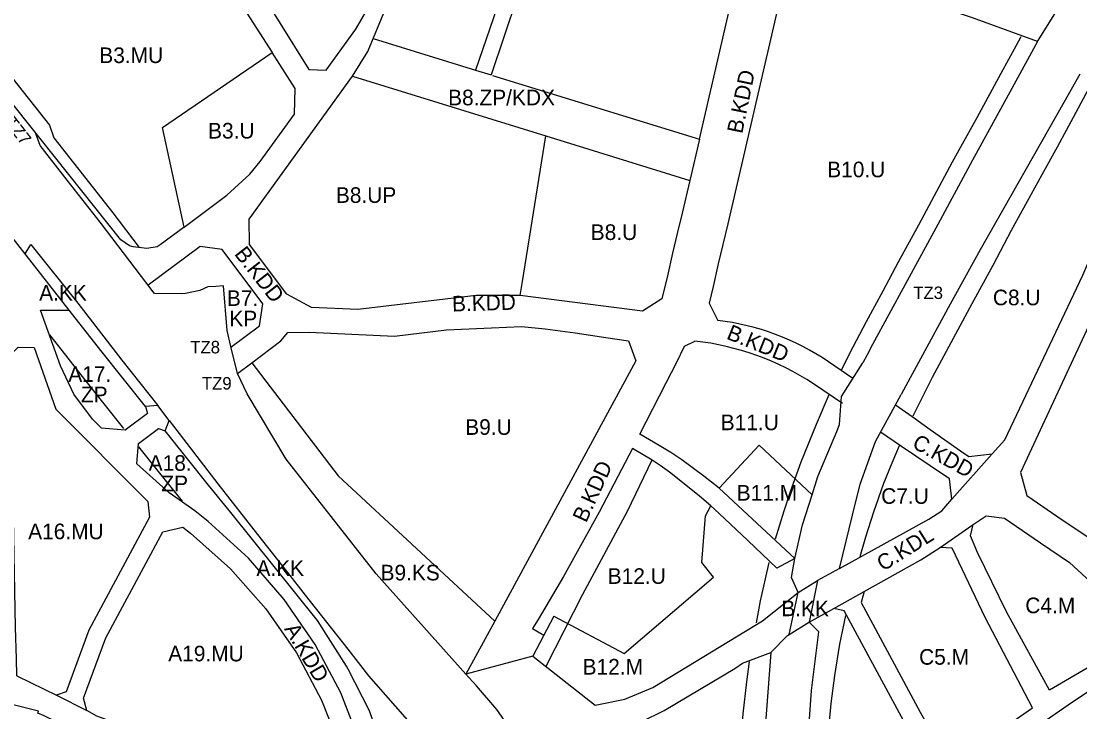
# Model space of a CAD drawing. Extents: x -292612 to -290407, y 29458 to 30862.
# Drawn here: x -292209 to -291531, y 29911 to 30353 of the extents above; entities that cross this region are included whole.
import ezdxf

# ---------------------------------------------------------------- set-up
doc = ezdxf.new("R2010")
doc.units = 0
for name, color, linetype in [('linie_rozgraniczajace', 7, 'Continuous'), ('linie_zabudowy_obowiazujace', 7, 'Continuous'), ('oznaczenia_przeznaczen', 7, 'Continuous')]:
    doc.layers.add(name, color=color, linetype=linetype)

msp = doc.modelspace()

# ---------------------------------------------------------------- linework, layer by layer
at = {"layer": 'linie_rozgraniczajace'}
for p, q in [((-291868.5, 30467.98), (-291918.12, 30321.67)), ((-291859.38, 30464.34), (-291908.23, 30318.61)), ((-291983.72, 30341.92), (-291918.12, 30321.67)), ((-291918.12, 30321.67), (-291908.23, 30318.61)), ((-292178.26, 30167.91), (-292296.67, 30319.14)), ((-291996.9, 30317.77), (-291873.16, 30279.56)), ((-291907.27, 30318.32), (-291774.91, 30277.44)), ((-291873.16, 30279.56), (-291781, 30251.1)), ((-291676.62, 30124.26), (-291692.26, 30134.9)), ((-291683.21, 30108.18), (-291701.82, 30120.84)), ((-291662.21, 30083.74), (-291645.75, 30113.93)), ((-291613.24, 30046.83), (-291587.37, 30075.86)), ((-291762.11, 30053.91), (-291713.69, 30008.82)), ((-291620.76, 30015.91), (-291599.54, 30030.65)), ((-291711.61, 29987.19), (-291699.22, 29994.8)), ((-291688.74, 29976.95), (-291669.49, 29987.68)), ((-291905.83, 29968.86), (-291924.29, 29934.77)), ((-291868.11, 29971.88), (-291881.54, 29946.35)), ((-291717.35, 29960.15), (-291704.43, 29968.23)), ((-291881.54, 29946.35), (-291924.29, 29934.77)), ((-292186.33, 29921.37), (-292166.99, 29911.62)), ((-291812.1, 29904.25), (-291797.36, 29911.59))]:
    msp.add_line(p, q, dxfattribs=at)
for points in [[(-292120.42, 30508.09), (-292127.95, 30497.99), (-292123.99, 30482.41), (-292115.47, 30467.94), (-292024.96, 30322.03), (-292013.84, 30321.64), (-291994.87, 30347.91), (-291984.86, 30365.19), (-291980.5, 30376.62), (-291946.51, 30485.4), (-291943.39, 30494.87)], [(-291996.9, 30317.77), (-291987.17, 30333.65), (-291975.8, 30360.87), (-291971.05, 30373.34), (-291936.99, 30482.35), (-291933.72, 30492.28)], [(-292104.75, 30221.08), (-292119.95, 30209.73), (-292121.9, 30208.54), (-292128.67, 30207.44), (-292137.35, 30208.56), (-292139.58, 30209.07), (-292145.2, 30212.99), (-292221.03, 30308.3), (-292227.7, 30317.87), (-292239.51, 30337.34), (-292236.95, 30350.95), (-292118.95, 30424.55), (-292105.07, 30421.42), (-292048.46, 30333.06)], [(-291774.91, 30277.44), (-291744.32, 30409.82), (-291752.76, 30423.16)], [(-291705.68, 30398.89), (-291717.36, 30393.25), (-291756.65, 30223.21), (-291759.84, 30210), (-291762.77, 30197.66), (-291766.07, 30183.17), (-291768.63, 30172.4), (-291763.14, 30161.41)], [(-291558.46, 30340.08), (-291600, 30355.26), (-291608.33, 30358.01), (-291621.44, 30362.85), (-291641.87, 30370.35), (-291650.9, 30373.9), (-291652.24, 30374.21), (-291663.12, 30379.46), (-291705.68, 30398.89)], [(-291558.46, 30340.08), (-291546.23, 30359.4), (-291536.07, 30377.12)], [(-291558.46, 30340.08), (-291574.9, 30309.97), (-291600, 30264.01), (-291622.25, 30222.87), (-291663.96, 30145.97), (-291667.53, 30139.38), (-291670.29, 30134.33)], [(-292104.75, 30221.08), (-292118.54, 30284.94), (-292048.46, 30333.06)], [(-292104.75, 30221.08), (-292077.28, 30241.6), (-292062.55, 30255.09), (-292056.04, 30263.18), (-292034.16, 30293.49), (-292033.7, 30310.01), (-292048.46, 30333.06)], [(-291889.69, 30177.45), (-291917.73, 30177.45), (-291993.43, 30168.33), (-292023.1, 30169.7), (-292039.07, 30178.18), (-292062.89, 30210.07), (-292063.02, 30226.19), (-291996.9, 30317.77)], [(-291531.35, 30319.11), (-291541.63, 30300.98), (-291595.06, 30206.69), (-291614.29, 30171.79), (-291633.29, 30136.77), (-291642.72, 30119.48), (-291645.75, 30113.93)], [(-291587.37, 30075.86), (-291579.39, 30084.83), (-291529.48, 30190.45), (-291516.54, 30220.35), (-291488.83, 30274.64), (-291492.29, 30289.54)], [(-292070.55, 30127.38), (-292074.87, 30144.76), (-292077.26, 30154.89), (-292079.56, 30183.45), (-292084.41, 30183.2), (-292089.64, 30182.94), (-292094.67, 30180.47), (-292103.75, 30178.69), (-292106.67, 30178.44), (-292123.75, 30178.72), (-292124.51, 30179.63), (-292158.36, 30224.28), (-292179.5, 30251.23), (-292196.93, 30273.47), (-292199.96, 30282.17), (-292200.04, 30282.28)], [(-291889.69, 30177.45), (-291888.2, 30186.35), (-291873.16, 30279.56)], [(-291774.91, 30277.44), (-291781, 30251.1)], [(-291467.65, 30260.81), (-291478.94, 30258.78), (-291538.4, 30130.5), (-291569.22, 30063.92), (-291565.18, 30049.18), (-291545.32, 30035.54), (-291525.45, 30022.09), (-291513.27, 30010.73), (-291511.12, 30008.52), (-291501.73, 29998.88), (-291486.94, 29983.17), (-291484.89, 29980.9)], [(-291781, 30251.1), (-291785.85, 30230.11), (-291789.02, 30216.98), (-291791.99, 30204.46), (-291795.29, 30189.97), (-291798.82, 30175.13), (-291811.39, 30167.38), (-291889.69, 30177.45)], [(-292206.57, 30204.07), (-292202.85, 30210), (-292172.79, 30172.5), (-292144.5, 30135.83), (-292121.54, 30106.87)], [(-292074.76, 30144.3), (-292056.44, 30157.99), (-292054.41, 30171.98), (-292080.42, 30206.8), (-292094.41, 30208.83), (-292127.76, 30183.92)], [(-292129.38, 30106.3), (-292128.25, 30101.86), (-292142.54, 30091.18), (-292157.6, 30092.29), (-292160.64, 30095.36), (-292163.33, 30098.18), (-292175.3, 30114.17), (-292183.86, 30132.22), (-292196.61, 30167.98), (-292178.26, 30167.91)], [(-292129.38, 30106.3), (-292158.04, 30142.09), (-292178.26, 30167.91)], [(-292061.46, 30134.27), (-292042.75, 30148.24), (-292038.23, 30153.72), (-292024.75, 30153.76), (-291970.1, 30151.23), (-291936.76, 30155.35), (-291888.85, 30157.41), (-291873.63, 30156.08), (-291854.46, 30153.46), (-291834.86, 30150.45), (-291820.2, 30148.39), (-291815.58, 30135.56), (-291905.83, 29968.86)], [(-292211.9, 29933.7), (-292212.1, 29944.67), (-292212.64, 29964.75), (-292215.94, 30139.28), (-292211.03, 30144.17), (-292200.78, 30143.94), (-292186.77, 30104.64), (-292127.96, 30045.4), (-292126.81, 30035.44), (-292165.71, 29962.95), (-292180.32, 29923.57), (-292186.33, 29921.37)], [(-291762.11, 30053.91), (-291771.94, 30061.7), (-291786.04, 30072.08), (-291793.16, 30076.89), (-291800.59, 30081.25), (-291813.01, 30088.47), (-291796.12, 30121.52), (-291789.37, 30134.74), (-291784.38, 30144.98), (-291777.75, 30148.16)], [(-291924.29, 29934.77), (-291981.7, 29999.05), (-292039.42, 30072.44), (-292064.36, 30114.3), (-292070.55, 30127.38), (-292061.46, 30134.27)], [(-292061.46, 30134.27), (-292006.14, 30061.83), (-291905.83, 29968.86)], [(-291685.13, 30094.69), (-291683.93, 30112.64), (-291670.29, 30134.33)], [(-292116.85, 30090.65), (-292114.36, 30097.25), (-292121.54, 30106.87), (-292129.38, 30106.3)], [(-291649.3, 30107.41), (-291636.63, 30098.26), (-291634.83, 30096.98), (-291627.14, 30091.49), (-291617.74, 30084.83), (-291607.83, 30077.96), (-291602.33, 30074.15), (-291587.37, 30075.86)], [(-292114.36, 30097.25), (-292083.21, 30056.76), (-292057.73, 30024.34), (-292038.64, 30000), (-292027.25, 29985.48), (-292000, 29950.73), (-291986.69, 29933.75), (-291946.41, 29887.93)], [(-291978.9, 29881.84), (-291991.76, 29890.16), (-292004.47, 29922.77), (-292020.82, 29953.71), (-292040.59, 29982.6), (-292063.52, 30009.04), (-292089.32, 30032.69), (-292097.85, 30039.41), (-292114.29, 30050.9), (-292134.97, 30069.53), (-292134, 30082.58), (-292121.07, 30092.24), (-292116.85, 30090.65)], [(-291975.93, 29882.22), (-291986.13, 29911.24), (-291999.65, 29938.08), (-292000.85, 29939.93), (-292019.3, 29969.25), (-292074.88, 30038.31), (-292089.02, 30055.89), (-292116.85, 30090.65)], [(-291702.6, 30049.7), (-291699.15, 30061.45), (-291686.98, 30090.3), (-291685.13, 30094.69)], [(-291613.24, 30046.83), (-291614.85, 30059.93), (-291627.24, 30068.23), (-291645.51, 30080.53), (-291658.87, 30089.86)], [(-291685.2, 30002.54), (-291676.93, 30036.58), (-291672.03, 30056.58), (-291662.21, 30083.74)], [(-291767.6, 30042.6), (-291774.84, 30048.89), (-291783.5, 30055.95), (-291794, 30064.19), (-291799.97, 30068.56), (-291805.1, 30071.84), (-291817.59, 30079.46), (-291839.08, 30038.57), (-291861.86, 29997.35), (-291878.07, 29969.8), (-291881.7, 29964), (-291874.52, 29959.69)], [(-291762.11, 30053.91), (-291736.51, 30081.4), (-291702.6, 30049.7)], [(-291713.69, 30008.82), (-291708.8, 30030.5), (-291702.6, 30049.7)], [(-291868.11, 29971.88), (-291823.06, 29948.02), (-291765.88, 29997.02), (-291773.25, 30006.36), (-291771.03, 30036.32), (-291767.6, 30042.6)], [(-291713.69, 30008.82), (-291725.4, 30002.71), (-291743.85, 30020.51), (-291762.23, 30037.82), (-291767.6, 30042.6)], [(-291685.2, 30002.54), (-291627.96, 30034.17), (-291619.74, 30039.52), (-291613.24, 30046.83)], [(-291599.54, 30030.65), (-291591.28, 30036.14), (-291579.52, 30034.77), (-291556.59, 30019.01), (-291537.95, 30006.4), (-291527.26, 29996.43), (-291525.45, 29994.57), (-291516.18, 29985.05), (-291501.64, 29969.61), (-291498.53, 29966.16)], [(-292166.99, 29911.62), (-292169.08, 29919.34), (-292154.75, 29958), (-292118.26, 30025.98), (-292105.47, 30028.88), (-292100.59, 30025.07), (-292075.06, 30002.23), (-292052.38, 29976.58), (-292032.83, 29948.45), (-292016.7, 29918.24), (-292004.2, 29886.35), (-292011.57, 29877.83)], [(-291498.53, 29966.16), (-291499.34, 29956.55), (-291524.02, 29940.24), (-291550.75, 29924.57), (-291578.39, 29974.64), (-291596.85, 30012.7), (-291601.37, 30023.33), (-291599.54, 30030.65)], [(-291669.49, 29987.68), (-291671.27, 29980.66), (-291633.48, 29910.49), (-291617.58, 29881.84), (-291604.81, 29883.45), (-291561.59, 29913.3), (-291592.04, 29971.03), (-291613.04, 30015.42), (-291620.76, 30015.91)], [(-291669.49, 29987.69), (-291633.08, 30008), (-291620.76, 30015.91)], [(-291711.61, 29987.19), (-291715.94, 29996.71), (-291713.69, 30008.82)], [(-291685.2, 30002.54), (-291699.22, 29994.8), (-291704.52, 29968.14)], [(-291881.54, 29946.35), (-291841.55, 29915.05), (-291822.6, 29918.89), (-291804.72, 29926.18), (-291734.47, 29968.95), (-291711.61, 29987.19)], [(-291729.07, 29948.78), (-291718.48, 29959.59), (-291717.36, 29960.14), (-291711.61, 29987.19)], [(-291704.52, 29968.14), (-291688.74, 29976.95)], [(-291628.04, 29874), (-291644.01, 29904.73), (-291682.1, 29975.46), (-291688.74, 29976.95)], [(-291708.15, 29822.07), (-291707.18, 29866.32), (-291703.04, 29924.32), (-291698.38, 29961.89), (-291704.52, 29968.14)], [(-291797.36, 29911.59), (-291752.29, 29938.44), (-291747.28, 29941.87), (-291729.07, 29948.78)], [(-291729.07, 29948.78), (-291732.96, 29897.85), (-291733.22, 29856.93), (-291730.07, 29842.68), (-291731.09, 29838.65)], [(-291477.58, 29947.7), (-291488.85, 29948.52), (-291538.79, 29914.86), (-291582.58, 29884.55), (-291586.65, 29881.17), (-291590.07, 29876.95), (-291591.84, 29873.31), (-291598.51, 29856.15), (-291599.12, 29852.22), (-291614.65, 29844.03)], [(-292211.9, 29933.7), (-292194.24, 29925.25), (-292186.33, 29921.37)], [(-291819.45, 29783.2), (-291820.74, 29785.22), (-291845.84, 29824.54), (-291860.59, 29861.86), (-291867.85, 29889.42), (-291886.03, 29885.5), (-291897.71, 29902.45), (-291904.57, 29912.13), (-291917.59, 29927.44), (-291924.51, 29934.99)], [(-291997.89, 29864.27), (-292011.86, 29863.38), (-292018.37, 29863.29), (-292040.84, 29865.39), (-292047.97, 29865.95), (-292072.31, 29869.28), (-292095.86, 29873.28), (-292122.04, 29877.72), (-292138.55, 29880.13), (-292175.49, 29898.85), (-292194.21, 29908.17), (-292198.39, 29909.92), (-292198.03, 29911.14), (-292216.69, 29915.79), (-292234.71, 29910.07), (-292238.43, 29904.69), (-292222.57, 29886.61), (-292209.52, 29868.85), (-292202.01, 29856.35), (-292193.02, 29835.97), (-292186.08, 29825.88), (-292171.12, 29805.01)], [(-292011.57, 29877.83), (-292027.9, 29878.97), (-292098.18, 29889.69), (-292120.57, 29893.65), (-292130.23, 29896.77), (-292135.79, 29898.9), (-292147.1, 29903), (-292160.49, 29907.99), (-292166.99, 29911.62)]]:
    msp.add_lwpolyline(points, dxfattribs=at)
for centre, radius, start, end in [((-291781.98, 30003.03), 159.5, 55.77089, 83.2178), ((-291797.2, 29974.91), 174.34, 56.83251, 83.59559)]:
    msp.add_arc(centre, radius, start, end, dxfattribs=at)
at = {"layer": 'linie_zabudowy_obowiazujace'}
for points in [[(-292236.94, 30350.95), (-292217.25, 30319.88), (-292190.86, 30286.45), (-292188.03, 30278.34), (-292150.43, 30230.39), (-292133.52, 30208.07)], [(-291684.11, 30129.36), (-291676.51, 30144.38), (-291667.8, 30160.77), (-291657.33, 30180.4), (-291647.33, 30199), (-291634.46, 30222.64), (-291612.76, 30262.98), (-291597.13, 30291.46), (-291581.7, 30319.78), (-291571.98, 30337.68), (-291568.93, 30343.3)], [(-291524.28, 30312.55), (-291535.69, 30291.32), (-291545.86, 30272.44), (-291555.61, 30254.64), (-291564.97, 30237.57), (-291575.28, 30218.88), (-291587.13, 30196.64), (-291600.39, 30172.08), (-291610.88, 30152.67), (-291625.85, 30124.88), (-291638.29, 30100.13)], [(-292143.29, 30092.23), (-292155.91, 30107.96), (-292168.22, 30123.49), (-292182.84, 30142.14), (-292190.7, 30152.18)], [(-291726.06, 30021.56), (-291720.65, 30039.36), (-291716.62, 30051.86), (-291709.72, 30070.88), (-291699.84, 30095.01), (-291691.77, 30114.01)], [(-292105.75, 30045.59), (-292121.11, 30064.67), (-292133.76, 30080.39)], [(-291647.07, 30081.04), (-291651.73, 30069.99), (-291656.93, 30056.87), (-291663.45, 30038.63), (-291668.63, 30022.58), (-291672.25, 30009.92)], [(-291805.28, 30071.96), (-291821.07, 30039.05), (-291849.6, 29985.87), (-291873.16, 29939.79)], [(-291738.41, 29967.59), (-291735.66, 29981.8), (-291732.54, 29995.92), (-291730.27, 30006.26)], [(-291681.39, 29972.33), (-291685.15, 29954.07), (-291688.33, 29934.01), (-291690.73, 29915.96), (-291692.92, 29893.15), (-291694.23, 29871.17), (-291694.5, 29854.67), (-291694.32, 29834.01), (-291693.03, 29810.03), (-291691.16, 29790.03), (-291688.57, 29768.51), (-291684.49, 29746.38), (-291681.15, 29729.67), (-291675.36, 29705.72), (-291668.28, 29680.34), (-291633.35, 29690.9), (-291578.24, 29707.36), (-291556.48, 29713.86)], [(-291748.86, 29832.89), (-291749.14, 29847.16), (-291749.27, 29862.73), (-291748.9, 29874.71), (-291748.03, 29892.08), (-291746.76, 29909.36), (-291744.41, 29930), (-291742.71, 29942.85)]]:
    msp.add_lwpolyline(points, dxfattribs=at)

# ---------------------------------------------------------------- texts
at = {"layer": 'oznaczenia_przeznaczen'}
for s, height, p in [('B3.MU', 10, (-292159.01, 30326.23)), ('B8.ZP/KDX', 10, (-291935.71, 30299.17)), ('B3.U', 10, (-292089.39, 30277.89)), ('B10.U', 10, (-291693.05, 30253.08)), ('B8.UP', 10, (-292007.56, 30236.68)), ('B8.U', 10, (-291844.42, 30212.92)), ('A.KK', 10, (-292197.51, 30174.11)), ('B7.', 10, (-292077.34, 30170.66)), ('TZ3', 8, (-291637.94, 30175.1)), ('C8.U', 10, (-291587, 30171.09)), ('KP', 10, (-292075.75, 30157.57)), ('TZ8', 8, (-292100.76, 30140.29)), ('A17.', 10, (-292178.86, 30122.05)), ('TZ9', 8, (-292093.32, 30117.09)), (' ZP', 10, (-292174.49, 30108.96)), ('B9.U', 10, (-291924.75, 30088.1)), ('B11.U', 10, (-291761.21, 30091.08)), ('A18.', 10, (-292127.39, 30065.07)), (' ZP', 10, (-292123.02, 30051.98)), ('B11.M', 10, (-291750.96, 30045.99)), ('C7.U', 10, (-291658.49, 30043.92)), ('A16.MU', 10, (-292204.54, 30021.25)), ('A.KK', 10, (-292058.42, 29997.76)), ('B9.KS', 10, (-291978.97, 29994.87)), ('B12.U', 10, (-291833.55, 29992.65)), ('B.KK', 10, (-291722.43, 29971.96)), ('C4.M', 10, (-291566.24, 29973.86)), ('A19.MU', 10, (-292114.87, 29943.02)), ('C5.M', 10, (-291634.24, 29940.89)), ('B12.M', 10, (-291849.62, 29934.56))]:
    msp.add_text(s, height=height, dxfattribs=at).set_placement(p)
for s, height, rotation, p in [('B.KDD', 10, 78.35526, (-291747.48, 30280.59)), ('TZ7', 8, 307.87498, (-292219.92, 30287.92)), ('B.KDD', 10, 308.05577, (-292072.98, 30203.88)), ('B.KDD', 10, 1.72895, (-291933.08, 30167.05)), ('B.KDD', 10, 337.9566, (-291758.12, 30149.81)), ('C.KDD', 10, 331.09082, (-291639.36, 30080.31)), ('B.KDD', 10, 65.28594, (-291847.37, 30031.33)), ('C.KDL', 10, 32.125, (-291657.32, 30000.4)), ('A.KDD', 10, 300.62436, (-292040.89, 29963.83))]:
    msp.add_text(s, height=height, rotation=rotation, dxfattribs=at).set_placement(p)

doc.saveas('drawing.dxf')
